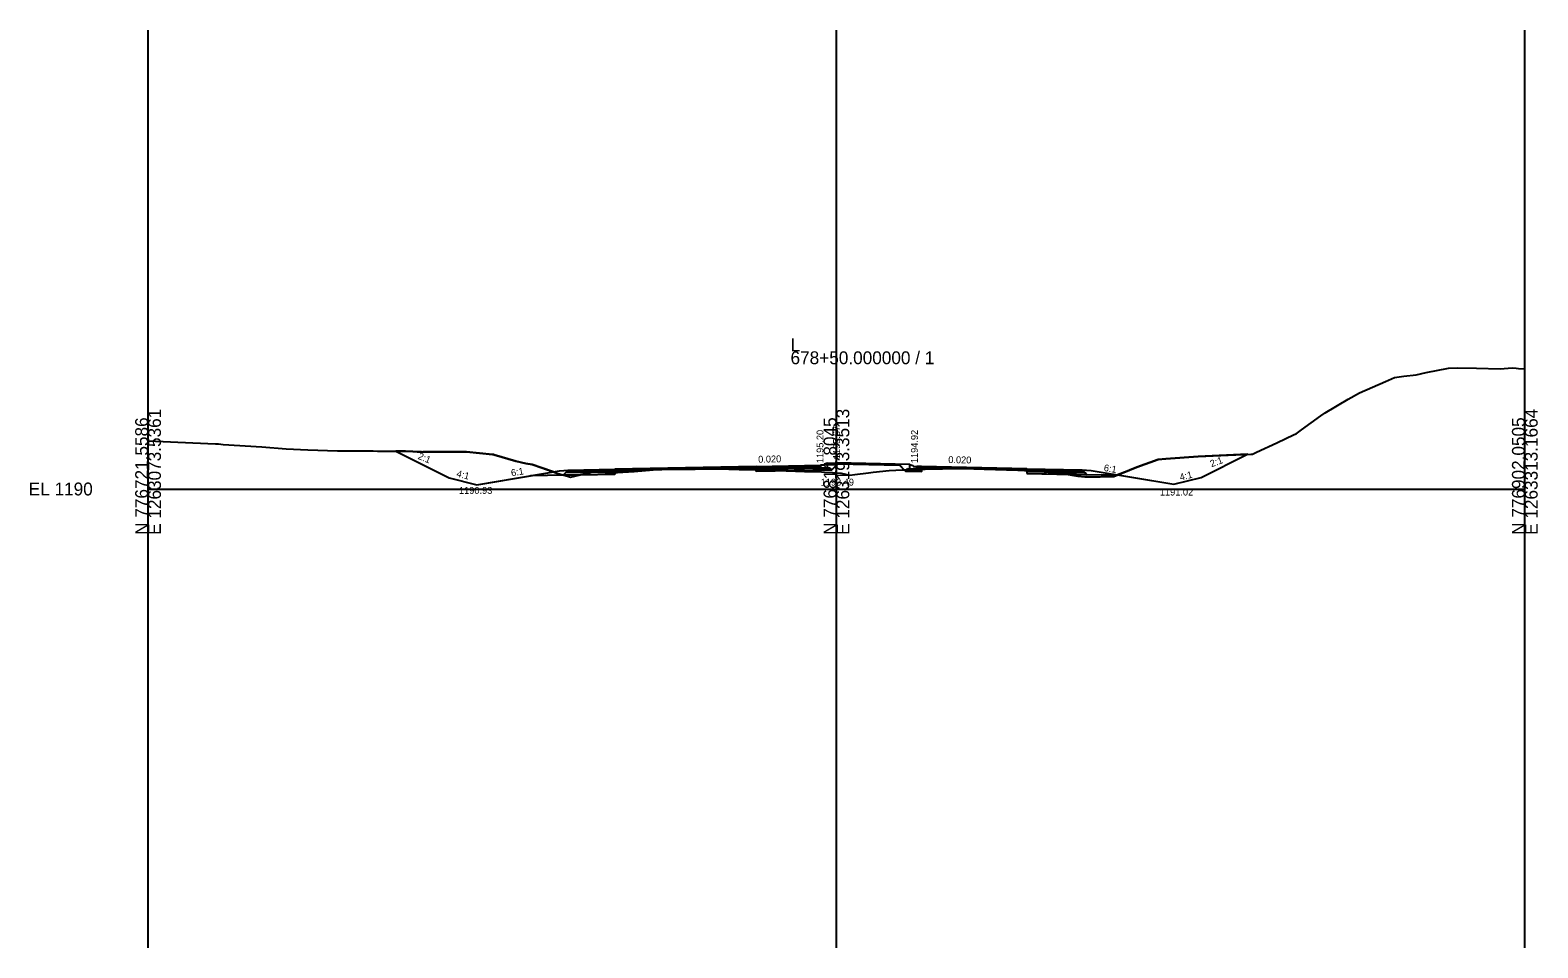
# Model space of a CAD drawing. Extents: x -41 to 1262860, y -100 to 777489.
# Drawn here: x 474.3 to 802.8, y 2515 to 2715 of the extents above; entities that cross this region are included whole.
import ezdxf

# ---------------------------------------------------------------- set-up
doc = ezdxf.new("R2010")
doc.units = 0
for name, color, linetype in [('Exist Cross Section Cell', 7, 'Continuous'), ('Exist XS Center Line Elevation Label', 7, 'Continuous'), ('Exist XS Ground Line', 7, 'Continuous'), ('Prop CMT Pvmt Course 1', 7, 'Continuous'), ('Prop CMT Pvmt Surface', 7, 'Continuous'), ('Prop CMT Shld Paved Course 1', 7, 'Continuous'), ('Prop CMT Shld Paved Course 2', 7, 'Continuous'), ('Prop CMT Shld Paved Course 4', 7, 'Continuous'), ('Prop CMT Subgrade Earthwork', 7, 'Continuous'), ('Prop Conc Curb and Gutter', 7, 'Continuous'), ('Prop Conc Island Cover', 7, 'Continuous'), ('Prop XS Ditch Standard Text', 7, 'Continuous'), ('Prop XS Earthwork Shape', 7, 'Continuous'), ('Prop XS Elevation Labels', 7, 'Continuous'), ('Prop XS Exc Vertical Line 1', 7, 'Continuous'), ('Prop XS Exc Vertical Line 2', 7, 'Continuous'), ('Prop XS Exc Vertical Line 3', 7, 'Continuous'), ('Prop XS Finish Grade', 7, 'Continuous'), ('Prop XS Hydro Elevations', 7, 'Continuous'), ('Prop XS SE Text', 7, 'Continuous'), ('Prop XS Side Slope Text', 7, 'Continuous'), ('Scratch_Level_4', 7, 'Continuous'), ('Scratch_Level_6', 7, 'Continuous')]:
    doc.layers.add(name, color=color, linetype=linetype)

msp = doc.modelspace()

# ---------------------------------------------------------------- linework, layer by layer
at = {"layer": 'Exist Cross Section Cell'}
for p, q in [((650, 2615), (650, 2645)), ((500, 2615), (650, 2615)), ((650, 2615), (800, 2615))]:
    msp.add_line(p, q, dxfattribs=at)
at = {"layer": 'Exist XS Ground Line'}
msp.add_lwpolyline([(500, 2625.5), (509.76, 2625.05), (514.67, 2624.86), (515.29, 2624.82), (515.36, 2624.81), (516.33, 2624.73), (524.8, 2624.16), (530.06, 2623.74), (534.82, 2623.5), (541.26, 2623.34), (548.61, 2623.3), (549.02, 2623.29), (549.97, 2623.28), (556.11, 2623.22), (557.69, 2623.17), (558.61, 2623.1), (559.3, 2623.07), (559.54, 2623.07), (559.73, 2623.04), (559.98, 2623.07), (562.03, 2623.1), (568.15, 2623.09), (569.4, 2623.11), (575.08, 2622.52), (575.38, 2622.49), (575.42, 2622.48), (580.17, 2621.08), (582.31, 2620.57), (583.67, 2620.32), (585.78, 2619.62), (589.07, 2618.46), (590.42, 2618.1), (592.08, 2617.6), (595.49, 2618.39), (596.79, 2618.76), (597.79, 2618.84), (599.12, 2618.93), (599.41, 2618.81), (600.29, 2618.41), (600.54, 2618.43), (601.03, 2618.51), (605.9, 2618.83), (610.91, 2619.23), (619.2, 2619.32), (622.98, 2619.36), (626.57, 2619.29), (635.18, 2619.13), (643.06, 2618.85), (646.74, 2618.71), (647.43, 2618.68), (649.15, 2618.6), (649.79, 2618.5), (650.91, 2618.48), (651.04, 2618.45), (652.89, 2618.02), (654.02, 2618.16), (656.96, 2618.52), (658.01, 2618.64), (661.5, 2619.02), (662.94, 2619.1), (665.6, 2619.24), (673.08, 2619.36), (677.71, 2619.44), (682.22, 2619.32), (689.52, 2619.13), (691.01, 2619.03), (693.35, 2618.88), (697.07, 2618.59), (699.61, 2618.29), (702.59, 2617.8), (704.13, 2617.64), (707.45, 2617.64), (710.48, 2617.76), (713.34, 2618.87), (713.86, 2619.07), (715.49, 2619.73), (720.08, 2621.41), (721.76, 2621.6), (728.79, 2622.1), (740.29, 2622.6), (740.63, 2622.61), (741.56, 2623.05), (745.98, 2625.06), (749.74, 2626.86), (750.17, 2627.05), (750.46, 2627.25), (751.36, 2627.92), (755.54, 2630.98), (756.49, 2631.6), (761.54, 2634.56), (764.01, 2635.93), (769.64, 2638.43), (771.6, 2639.33), (773.63, 2639.58), (776.33, 2639.86), (778.51, 2640.4), (783.39, 2641.36), (785.28, 2641.43), (789.49, 2641.3), (794.63, 2641.17), (797.22, 2641.44), (798.1, 2641.3), (798.62, 2641.27), (800, 2641.16)], dxfattribs=at)
at = {"layer": 'Prop CMT Pvmt Course 1'}
for p, q in [((632.5, 2619.65), (646.54, 2619.93)), ((646.54, 2619.93), (646.54, 2620.18)), ((667.5, 2619.9), (667.5, 2619.65)), ((668.5, 2619.63), (667.5, 2619.65))]:
    msp.add_line(p, q, dxfattribs=at)
for points in [[(601.69, 2619.29), (601.69, 2619.04), (632.5, 2619.65), (632.5, 2619.65), (632.5, 2619.9), (632.5, 2619.9), (632.5, 2619.9), (601.69, 2619.29), (601.69, 2619.29)], [(691.5, 2619.42), (691.5, 2619.42), (668.5, 2619.88), (668.5, 2619.88), (668.5, 2619.88), (668.5, 2619.88), (668.5, 2619.63), (668.5, 2619.63), (668.5, 2619.63), (691.5, 2619.17), (691.5, 2619.42)]]:
    msp.add_lwpolyline(points, dxfattribs=at)
at = {"layer": 'Prop CMT Pvmt Surface'}
for p, q in [((591.53, 2619.08), (601.69, 2619.29)), ((601.69, 2619.29), (632.5, 2619.9)), ((632.5, 2619.9), (646.54, 2620.18)), ((668.5, 2619.88), (667.5, 2619.9)), ((668.5, 2619.88), (691.5, 2619.42)), ((691.5, 2619.42), (703.5, 2619.18))]:
    msp.add_line(p, q, dxfattribs=at)
at = {"layer": 'Prop CMT Shld Paved Course 1'}
for p, q in [((591.28, 2618.83), (591.53, 2619.08)), ((601.69, 2619.04), (591.28, 2618.83)), ((597.69, 2619.21), (597.69, 2619.21)), ((601.69, 2619.29), (601.69, 2619.29)), ((601.69, 2619.29), (601.69, 2619.29)), ((601.69, 2619.29), (601.69, 2619.04)), ((601.69, 2619.04), (601.69, 2619.04)), ((691.5, 2619.42), (691.5, 2619.42)), ((691.5, 2619.42), (691.5, 2619.42)), ((691.5, 2619.42), (691.5, 2619.17)), ((691.5, 2619.17), (691.5, 2619.17)), ((691.5, 2619.17), (703.75, 2618.93)), ((703.75, 2618.93), (703.5, 2619.18))]:
    msp.add_line(p, q, dxfattribs=at)
at = {"layer": 'Prop CMT Shld Paved Course 2'}
for p, q in [((590.94, 2618.49), (591.28, 2618.83)), ((601.69, 2618.7), (590.94, 2618.49)), ((597.43, 2618.95), (597.43, 2618.95)), ((601.69, 2619.04), (605.9, 2619.12)), ((601.69, 2619.04), (601.69, 2619.04)), ((601.69, 2619.04), (601.69, 2619.04)), ((601.69, 2619.04), (601.69, 2618.7)), ((601.69, 2618.7), (601.69, 2619.04)), ((601.69, 2619.04), (601.69, 2619.04)), ((604.91, 2618.77), (601.69, 2618.7)), ((601.69, 2618.7), (601.69, 2618.7)), ((605.9, 2618.83), (604.91, 2618.77)), ((604.91, 2618.77), (604.91, 2618.77)), ((610.76, 2619.22), (605.9, 2618.83)), ((605.9, 2619.12), (610.91, 2619.22)), ((605.9, 2619.12), (605.9, 2619.12)), ((605.9, 2618.83), (605.9, 2618.83)), ((610.91, 2619.22), (610.76, 2619.22)), ((610.91, 2619.22), (619.2, 2619.39)), ((611.84, 2619.24), (610.91, 2619.22)), ((610.91, 2619.22), (610.91, 2619.22)), ((619.2, 2619.32), (611.84, 2619.24)), ((611.84, 2619.24), (611.84, 2619.24)), ((619.2, 2619.39), (622.98, 2619.46)), ((619.2, 2619.39), (619.2, 2619.39)), ((622.98, 2619.36), (619.2, 2619.32)), ((619.2, 2619.32), (619.2, 2619.32)), ((622.98, 2619.46), (626.57, 2619.53)), ((626.57, 2619.29), (622.98, 2619.36)), ((626.57, 2619.53), (632.5, 2619.65)), ((626.57, 2619.53), (626.57, 2619.53)), ((628.8, 2619.25), (626.57, 2619.29)), ((626.57, 2619.29), (626.57, 2619.29)), ((632.5, 2619.32), (628.8, 2619.25)), ((628.8, 2619.25), (628.8, 2619.25)), ((632.5, 2619.65), (632.5, 2619.65)), ((632.5, 2619.65), (632.5, 2619.65)), ((632.5, 2619.65), (632.5, 2619.32)), ((632.5, 2619.32), (646.54, 2619.6)), ((632.5, 2619.32), (632.5, 2619.32)), ((646.54, 2619.93), (646.54, 2619.6)), ((646.54, 2619.6), (646.54, 2619.6)), ((667.5, 2619.32), (667.5, 2619.65)), ((668.5, 2619.3), (667.5, 2619.32)), ((673.08, 2619.54), (668.5, 2619.63)), ((668.5, 2619.63), (668.5, 2619.63)), ((668.5, 2619.63), (668.5, 2619.63)), ((668.5, 2619.63), (668.5, 2619.63)), ((668.5, 2619.63), (668.5, 2619.3)), ((668.5, 2619.3), (668.5, 2619.3)), ((668.5, 2619.3), (668.88, 2619.29)), ((668.88, 2619.29), (673.08, 2619.36)), ((668.88, 2619.29), (668.88, 2619.29)), ((668.88, 2619.29), (668.88, 2619.29)), ((677.71, 2619.45), (673.08, 2619.54)), ((673.08, 2619.54), (673.08, 2619.54)), ((673.08, 2619.54), (673.08, 2619.54)), ((673.08, 2619.36), (677.71, 2619.44)), ((673.08, 2619.36), (673.08, 2619.36)), ((682.22, 2619.36), (677.71, 2619.45)), ((677.71, 2619.44), (682.22, 2619.32)), ((689.52, 2619.21), (682.22, 2619.36)), ((682.22, 2619.36), (682.22, 2619.36)), ((682.22, 2619.32), (682.22, 2619.32)), ((682.22, 2619.32), (689.52, 2619.13)), ((691.01, 2619.18), (689.52, 2619.21)), ((689.52, 2619.21), (689.52, 2619.21)), ((689.52, 2619.13), (689.52, 2619.13)), ((689.52, 2619.13), (691.01, 2619.03)), ((691.5, 2619.17), (691.01, 2619.18)), ((691.01, 2619.18), (691.01, 2619.18)), ((691.01, 2619.03), (691.01, 2619.03)), ((691.01, 2619.03), (691.5, 2619)), ((691.5, 2619.17), (691.5, 2619.17)), ((691.5, 2619.17), (691.5, 2619.17)), ((691.5, 2619.17), (691.5, 2618.84)), ((691.5, 2619), (691.5, 2619.17)), ((691.5, 2619.17), (691.5, 2619.17)), ((691.5, 2618.84), (691.5, 2618.84)), ((691.5, 2618.84), (704.09, 2618.59)), ((704.09, 2618.59), (703.75, 2618.93))]:
    msp.add_line(p, q, dxfattribs=at)
at = {"layer": 'Prop CMT Shld Paved Course 4'}
for p, q in [((590.94, 2618.49), (590.47, 2618.02)), ((596.59, 2618.6), (596.59, 2618.6)), ((597.09, 2618.61), (597.09, 2618.61)), ((604.91, 2618.77), (601.69, 2618.55)), ((601.69, 2618.7), (601.69, 2618.7)), ((601.69, 2618.7), (601.69, 2618.7)), ((601.69, 2618.7), (601.69, 2618.25)), ((628.8, 2619.25), (632.5, 2619.18)), ((632.5, 2619.32), (632.5, 2618.86)), ((632.5, 2618.86), (648.99, 2619.19)), ((646.54, 2619.6), (648.54, 2619.64)), ((648.54, 2619.64), (648.99, 2619.19)), ((665.5, 2619.36), (665.05, 2618.91)), ((668.5, 2618.84), (665.05, 2618.91)), ((667.5, 2619.32), (665.5, 2619.36)), ((668.5, 2618.84), (668.5, 2619.3)), ((668.88, 2619.29), (668.5, 2619.29)), ((691.5, 2618.84), (691.5, 2618.84)), ((691.5, 2618.84), (691.5, 2618.84)), ((691.5, 2618.84), (691.5, 2618.38)), ((704.56, 2618.12), (704.09, 2618.59)), ((590.47, 2618.02), (601.69, 2618.25)), ((691.5, 2618.38), (704.56, 2618.12))]:
    msp.add_line(p, q, dxfattribs=at)
at = {"layer": 'Prop CMT Subgrade Earthwork'}
for p, q in [((601.69, 2618.55), (601.69, 2618.25)), ((648.99, 2619.19), (632.5, 2618.86)), ((632.5, 2618.86), (632.5, 2619.18)), ((648.99, 2619.19), (650.46, 2620.66)), ((665.05, 2618.91), (663.56, 2620.4)), ((665.05, 2618.91), (668.5, 2618.84)), ((668.5, 2618.84), (668.5, 2619.29)), ((691.5, 2619), (691.5, 2618.38)), ((601.69, 2618.25), (583.34, 2617.88)), ((691.5, 2618.38), (711.78, 2617.98))]:
    msp.add_line(p, q, dxfattribs=at)
at = {"layer": 'Prop Conc Curb and Gutter'}
for p, q in [((647.23, 2620.2), (646.54, 2620.18)), ((646.54, 2620.18), (646.54, 2619.6)), ((646.54, 2619.6), (648.04, 2619.63)), ((647.29, 2620.28), (647.29, 2620.26)), ((648.04, 2620.63), (647.39, 2620.41)), ((648.04, 2619.63), (648.04, 2620.63)), ((648.04, 2619.63), (648.04, 2619.63)), ((666, 2620.35), (666.65, 2620.13)), ((666, 2619.35), (666, 2620.35)), ((667.5, 2619.32), (666, 2619.35)), ((666.75, 2619.99), (666.75, 2619.98)), ((666.81, 2619.92), (667.5, 2619.9)), ((667.5, 2619.32), (667.5, 2619.9))]:
    msp.add_line(p, q, dxfattribs=at)
for centre, radius, start, end in [((647.22, 2620.26), 0.0625, 271.1458, 360), ((647.43, 2620.28), 0.146, 108.435, 180), ((666.6, 2619.99), 0.146, 0, 71.565), ((666.81, 2619.98), 0.0625, 180, 268.8542)]:
    msp.add_arc(centre, radius, start, end, dxfattribs=at)
at = {"layer": 'Prop Conc Island Cover'}
for p, q in [((648.04, 2620.63), (650, 2620.67)), ((648.04, 2620.37), (648.04, 2620.37)), ((666, 2620.35), (650, 2620.67))]:
    msp.add_line(p, q, dxfattribs=at)
at = {"layer": 'Prop XS Earthwork Shape'}
for points in [[(553.98, 2623.24), (565.59, 2617.44), (571.63, 2615.93), (583.34, 2617.88), (588.36, 2618.71), (585.78, 2619.62), (583.67, 2620.32), (582.31, 2620.57), (580.17, 2621.08), (575.42, 2622.48), (575.38, 2622.49), (575.08, 2622.52), (569.4, 2623.11), (568.15, 2623.09), (562.03, 2623.1), (559.98, 2623.07), (559.73, 2623.04), (559.54, 2623.07), (559.3, 2623.07), (558.61, 2623.1), (557.69, 2623.17), (556.11, 2623.22)], [(711.25, 2618.06), (711.78, 2617.98), (723.5, 2616.02), (729.5, 2617.52), (739.58, 2622.56), (728.79, 2622.1), (721.76, 2621.6), (720.08, 2621.41), (715.49, 2619.73), (713.86, 2619.07), (713.34, 2618.87)], [(590.47, 2618.02), (583.34, 2617.88), (588.36, 2618.71), (589.07, 2618.46), (590.42, 2618.1), (590.52, 2618.07)], [(596.79, 2618.76), (597.79, 2618.84), (599.12, 2618.93), (599.41, 2618.81), (600.29, 2618.41), (600.54, 2618.43), (601.03, 2618.51), (601.69, 2618.55), (601.69, 2618.25), (594.22, 2618.1), (595.49, 2618.39)], [(632.5, 2619.18), (635.18, 2619.13), (639.07, 2618.99), (632.5, 2618.86)], [(646.74, 2618.71), (647.43, 2618.68), (649.15, 2618.6), (649.79, 2618.5), (650.91, 2618.48), (651.04, 2618.45), (652.89, 2618.02), (654.02, 2618.16), (656.96, 2618.52), (658.01, 2618.64), (661.5, 2619.02), (662.94, 2619.1), (664.77, 2619.19), (663.82, 2620.14), (650.21, 2620.42), (648.99, 2619.19), (639.07, 2618.99), (643.06, 2618.85)], [(664.77, 2619.19), (665.6, 2619.24), (668.5, 2619.29), (668.5, 2618.84), (665.05, 2618.91)], [(691.5, 2618.38), (700.12, 2618.21), (699.61, 2618.29), (697.07, 2618.59), (693.35, 2618.88), (691.5, 2619)], [(590.52, 2618.07), (590.67, 2618.02), (590.47, 2618.02)], [(592.08, 2617.6), (594.22, 2618.1), (590.67, 2618.02)], [(702.59, 2617.8), (704.13, 2617.64), (707.45, 2617.64), (710.48, 2617.76), (711.06, 2617.99), (704.56, 2618.12), (700.12, 2618.21)], [(711.06, 2617.99), (711.25, 2618.06), (711.78, 2617.98)]]:
    msp.add_lwpolyline(points, close=True, dxfattribs=at)
at = {"layer": 'Prop XS Exc Vertical Line 1'}
msp.add_line((500, 2515), (500, 2715), dxfattribs=at)
at = {"layer": 'Prop XS Exc Vertical Line 2'}
msp.add_line((650, 2515), (650, 2715), dxfattribs=at)
at = {"layer": 'Prop XS Exc Vertical Line 3'}
msp.add_line((800, 2515), (800, 2715), dxfattribs=at)
at = {"layer": 'Prop XS Finish Grade'}
for p, q in [((553.98, 2623.24), (565.59, 2617.44)), ((729.5, 2617.52), (739.58, 2622.56)), ((571.63, 2615.93), (589.69, 2618.94)), ((589.69, 2618.94), (591.53, 2619.08)), ((591.53, 2619.08), (590.47, 2618.02)), ((703.5, 2619.18), (705.5, 2619.02)), ((703.5, 2619.18), (704.56, 2618.12)), ((705.5, 2619.02), (723.5, 2616.02)), ((565.59, 2617.44), (571.63, 2615.93)), ((723.5, 2616.02), (729.5, 2617.52))]:
    msp.add_line(p, q, dxfattribs=at)
at = {"layer": 'Scratch_Level_4'}
msp.add_line((800, 2515), (800, 2715), dxfattribs=at)
at = {"layer": 'Scratch_Level_6'}
msp.add_line((500, 2515), (500, 2715), dxfattribs=at)

# ---------------------------------------------------------------- texts
at = {"layer": 'Exist Cross Section Cell'}
for s, p in [('678+50.000000 / 1', (640, 2642.2)), ('L', (640, 2645)), ('EL 1190', (474, 2613.6))]:
    msp.add_text(s, height=2.8, dxfattribs=at).set_placement(p)
for s, p in [('E 1263073.5361', (502.8, 2605)), ('E 1263193.3513', (652.8, 2605)), ('E 1263313.1664', (802.8, 2605)), ('N 776721.5586', (500, 2605)), ('N 776811.8045', (650, 2605)), ('N 776902.0505', (800, 2605))]:
    msp.add_text(s, height=2.8, rotation=90, dxfattribs=at).set_placement(p)
at = {"layer": 'Exist XS Center Line Elevation Label'}
msp.add_text('1193.49', height=1.5, dxfattribs=at).set_placement((646.57, 2615.74))
at = {"layer": 'Prop XS Ditch Standard Text'}
for s, p in [('1190.93', (567.76, 2613.94)), ('1191.02', (720.48, 2613.58))]:
    msp.add_text(s, height=1.5, dxfattribs=at).set_placement(p)
at = {"layer": 'Prop XS Elevation Labels'}
for s, p in [('1195.20', (647.17, 2620.64)), ('1194.92', (667.75, 2620.64))]:
    msp.add_text(s, height=1.5, rotation=90, dxfattribs=at).set_placement(p)
at = {"layer": 'Prop XS Hydro Elevations'}
msp.add_text('1195.67', height=1.5, rotation=90, dxfattribs=at).set_placement((650.77, 2621.5))
at = {"layer": 'Prop XS SE Text'}
for rotation, p in [(1.1458, (632.96, 2620.73)), (358.8542, (674.36, 2620.66))]:
    msp.add_text('0.020', height=1.5, rotation=rotation, dxfattribs=at).set_placement(p)
at = {"layer": 'Prop XS Side Slope Text'}
for s, rotation, p in [('2:1', 337.4135, (558.66, 2621.61)), ('2:1', 20.1493, (731.73, 2619.73)), ('4:1', 345.9638, (567.11, 2617.7)), ('6:1', 9.4623, (579.21, 2617.75)), ('6:1', 350.5377, (708.18, 2618.93)), ('4:1', 14.0362, (724.98, 2616.81))]:
    msp.add_text(s, height=1.5, rotation=rotation, dxfattribs=at).set_placement(p)

doc.saveas('drawing.dxf')
